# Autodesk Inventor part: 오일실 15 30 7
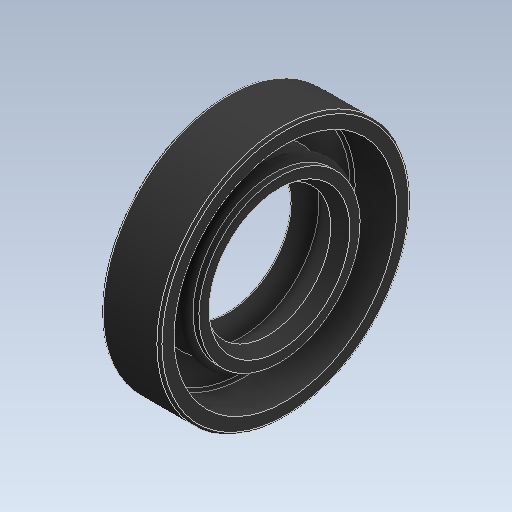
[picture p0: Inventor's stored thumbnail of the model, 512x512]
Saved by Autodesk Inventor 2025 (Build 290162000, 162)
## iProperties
Created: 2024-07
Part Number: 오일실 15 30 7
Material: 고무
Description: 오일-실
Document SubType Name: Modeling
Designer: 미서니
Density: 0.93 g/cm^3
Appearance: 기본값
Author: jhkim
Sending System: Autodesk Inventor 2025
Preprocessor: ST-DEVELOPER v20
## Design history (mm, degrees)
feature "Solid1"
node "솔리드1"
